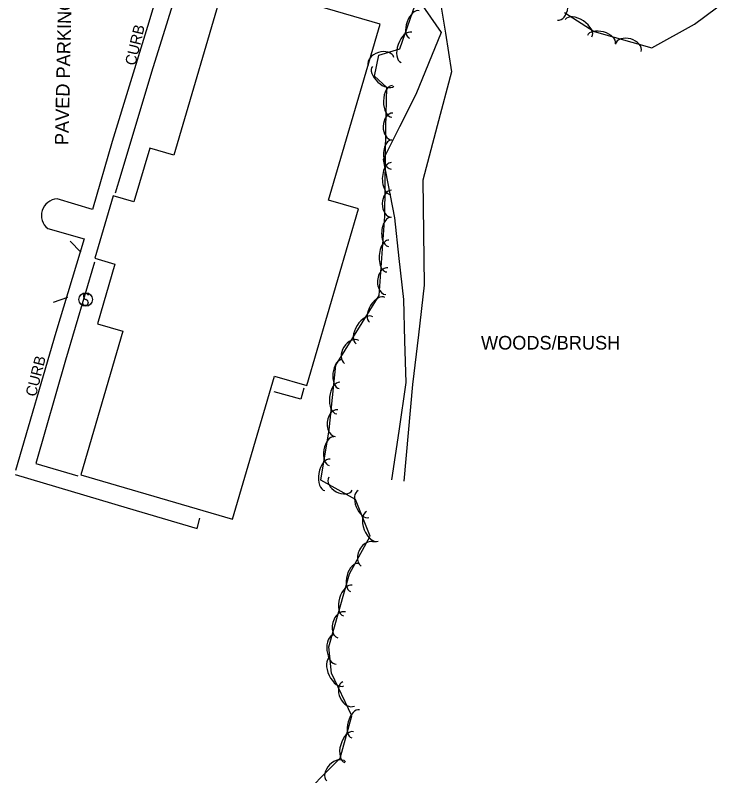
# Model space of a CAD drawing. Extents: x 978516 to 993312, y 1836504 to 1846212.
# Drawn here: x 992217.8 to 992474.8, y 1841361.8 to 1841641.6 of the extents above; entities that cross this region are included whole.
import ezdxf

# ---------------------------------------------------------------- set-up
doc = ezdxf.new("R2010")
doc.units = 0
for name, color, linetype in [('S_BUILDING', 7, 'Continuous'), ('S_CURB', 7, 'Continuous'), ('S_CURB_ANNOT', 7, 'Continuous'), ('S_PARKING', 7, 'Continuous'), ('S_PARKING_ANNOT', 7, 'Continuous'), ('S_SIDEWALK', 7, 'Continuous'), ('S_SIGN', 7, 'Continuous'), ('S_STREAM', 7, 'Continuous'), ('S_SURVEY_TEXT_ANNOT', 7, 'Continuous'), ('S_TREE', 7, 'Continuous')]:
    doc.layers.add(name, color=color, linetype=linetype)

msp = doc.modelspace()

# ---------------------------------------------------------------- linework, layer by layer
at = {"layer": 'S_BUILDING'}
msp.add_lwpolyline([(992295.19, 1841654.97), (992276.18, 1841590.11), (992267.27, 1841592.72), (992261.46, 1841572.9), (992253.87, 1841575.13), (992247.14, 1841552.19), (992254.47, 1841550.04), (992248.03, 1841528.07), (992257.43, 1841525.31), (992241.95, 1841472.52), (992297.77, 1841456.16), (992313.22, 1841508.85), (992325.09, 1841505.36), (992344.14, 1841570.36), (992333.06, 1841573.6), (992352.02, 1841638.31)], close=True, dxfattribs=at)
at = {"layer": 'S_CURB'}
for points in [[(992241.88, 1841554.44), (992237.97, 1841558.52)], [(992237.02, 1841537.8), (992231.7, 1841535.93)]]:
    msp.add_lwpolyline(points, dxfattribs=at)
at = {"layer": 'S_PARKING'}
for points in [[(992270.48, 1841694.38), (992281.96, 1841688.92), (992266.45, 1841637.41), (992253.5, 1841595.19), (992246.2, 1841570.07), (992233.19, 1841574.04)], [(992229.76, 1841563.11), (992243.1, 1841559.35), (992232.7, 1841524.85), (992217.88, 1841474.07)]]:
    msp.add_lwpolyline(points, dxfattribs=at)
msp.add_arc((992233.56, 1841567.92), 6.13, 93.4496, 231.6929, dxfattribs=at)
at = {"layer": 'S_SIDEWALK'}
for points in [[(992293.67, 1841654.91), (992279.9, 1841659.34), (992267.99, 1841620.64), (992256.59, 1841582.96), (992254.57, 1841576.2)], [(992246.96, 1841550.71), (992236.26, 1841514.68), (992225.32, 1841476.7), (992240.8, 1841472.12)], [(992323.95, 1841504.39), (992322.9, 1841500.34), (992313.05, 1841503)], [(992217.78, 1841472.61), (992258.99, 1841460.33), (992284.76, 1841452.72), (992285.74, 1841456.52)]]:
    msp.add_lwpolyline(points, dxfattribs=at)
at = {"layer": 'S_SIGN'}
msp.add_circle((992243.74, 1841537), 2.49, dxfattribs=at)
for centre, radius, start, end in [((992244.42, 1841538.33), 1.5, 167.1196, 241.9813), ((992243.81, 1841538.27), 0.95, 16.5258, 156.8957), ((992243.32, 1841535.66), 1.4, 358.6529, 73.7063), ((992243.58, 1841536.18), 1.28, 204.641, 335.359)]:
    msp.add_arc(centre, radius, start, end, dxfattribs=at)
at = {"layer": 'S_STREAM'}
for points in [[(992273.14, 1841723.34), (992280.91, 1841712.24), (992288.68, 1841701.14), (992309.73, 1841693.54), (992330.78, 1841685.93), (992345.76, 1841670.53), (992360.73, 1841655.13), (992374.51, 1841635.23), (992365.25, 1841612.49), (992359.21, 1841600.53), (992353.16, 1841588.56), (992357.3, 1841567.09), (992359, 1841552.08), (992360.7, 1841537.06), (992361.09, 1841521.8), (992361.48, 1841506.53), (992358.89, 1841488.58), (992356.29, 1841470.64)], [(992279.15, 1841723.05), (992299.02, 1841709.9), (992318.88, 1841696.74), (992330.75, 1841691.7), (992342.62, 1841686.67), (992351.74, 1841675.4), (992360.86, 1841664.14), (992373.77, 1841649.17), (992376.07, 1841634.98), (992378.37, 1841620.8), (992373.1, 1841600.86), (992367.83, 1841580.91), (992368.06, 1841561.59), (992368.3, 1841542.27), (992366.17, 1841524), (992364.03, 1841505.73), (992362.41, 1841487.93), (992360.79, 1841470.12)]]:
    msp.add_lwpolyline(points, dxfattribs=at)
at = {"layer": 'S_TREE'}
for points in [[(992419.97, 1841642.67), (992430.8, 1841635.64), (992452.11, 1841629.61), (992467.8, 1841638.34), (992487.8, 1841653.27)], [(992321.01, 1841351.83), (992337.31, 1841368.24), (992341.68, 1841383.78), (992334.14, 1841399.51), (992333.13, 1841409.25), (992340.82, 1841436.04), (992348.37, 1841449.95), (992342.99, 1841463.46), (992330.26, 1841470.56), (992333.35, 1841489.07), (992335.77, 1841512.81), (992351.75, 1841538.43), (992353.82, 1841567.69), (992354.2, 1841600.32), (992354.52, 1841615), (992350.03, 1841619.14), (992351.57, 1841626.88), (992359.3, 1841629.27), (992365, 1841645.4)]]:
    msp.add_lwpolyline(points, dxfattribs=at)
for centre, major_axis, ratio, start_param, end_param in [((992417.8, 1841644.69), (0.52, 4.93), 0.684432, 3.141593, 6.283185), ((992364.69, 1841638.16), (-1.78, -5.04), 0.540007, 3.141593, 6.283185), ((992425.09, 1841636.83), (-4.92, 3.2), 0.547716, 3.141593, 6.283185), ((992361.73, 1841629.8), (-1.96, -5.53), 0.549376, 3.141593, 6.283185), ((992433.53, 1841632.67), (-5.14, 1.46), 0.53871, 3.141593, 6.283185), ((992443.37, 1841629.62), (-4.77, 1.35), 0.682789, 3.141593, 6.283185), ((992352.41, 1841624.65), (-4.73, -1.46), 0.685052, 3.141593, 6.283185), ((992353.15, 1841619.16), (3.93, -3.63), 0.540555, 3.141593, 6.283185), ((992356.53, 1841609.92), (-0.13, -5.87), 0.549416, 3.141593, 6.283185), ((992356.58, 1841600.65), (-0.11, -4.95), 0.684484, 3.141593, 6.283185), ((992356.2, 1841590.38), (-0.06, -5.35), 0.540051, 3.141549, 6.283142), ((992356.1, 1841581.51), (-0.07, -5.87), 0.54942, 3.141548, 6.283141), ((992356.25, 1841572.25), (-0.06, -4.96), 0.684489, 3.14152, 6.283112), ((992355.53, 1841561.84), (-0.38, -5.33), 0.540044, 3.141343, 6.282936), ((992354.91, 1841552.99), (-0.41, -5.85), 0.549413, 3.141335, 6.282928), ((992354.51, 1841543.74), (-0.35, -4.94), 0.68448, 3.141171, 6.282764), ((992351, 1841533.23), (-2.83, -4.54), 0.540095, 3.141165, 6.282757), ((992346.31, 1841525.7), (-3.1, -4.98), 0.549465, 3.141151, 6.282743), ((992341.63, 1841517.71), (-2.62, -4.21), 0.684545, 3.14087, 6.282462), ((992337.57, 1841509.57), (-0.55, -5.31), 0.540437, 3.143089, 6.284681), ((992336.67, 1841500.76), (-0.6, -5.83), 0.549813, 3.143137, 6.284729), ((992335.99, 1841491.53), (-0.51, -4.93), 0.684978, 3.144121, 6.285714), ((992334.19, 1841481.23), (-0.88, -5.27), 0.540012, 3.141593, 6.283185), ((992332.73, 1841472.48), (-0.97, -5.79), 0.549381, 3.141593, 6.283185), ((992337.49, 1841469.26), (4.33, -2.41), 0.685263, 3.141593, 6.283185), ((992345.95, 1841461.76), (1.98, -4.97), 0.54026, 3.141593, 6.283185), ((992349.23, 1841453.52), (2.17, -5.45), 0.549632, 3.141593, 6.283185), ((992347.48, 1841443.31), (-2.36, -4.36), 0.684496, 3.141069, 6.282662), ((992342.66, 1841434.75), (-1.48, -5.13), 0.540559, 3.143354, 6.284946), ((992340.21, 1841426.24), (-1.62, -5.63), 0.549937, 3.143411, 6.285003), ((992337.91, 1841417.28), (-1.38, -4.76), 0.685131, 3.14457, 6.286163), ((992335.37, 1841408.21), (0.55, -5.32), 0.540098, 3.141593, 6.283185), ((992336.2, 1841400.12), (2.54, -5.29), 0.54968, 3.141593, 6.283185), ((992340.44, 1841391.88), (2.14, -4.47), 0.684812, 3.141593, 6.283185), ((992343.05, 1841380.84), (-1.44, -5.15), 0.540296, 3.140316, 6.281908), ((992340.65, 1841372.31), (-1.58, -5.65), 0.54967, 3.140275, 6.281867), ((992335.88, 1841363.42), (-3.49, -3.5), 0.685459, 3.144412, 6.286004)]:
    msp.add_ellipse(centre, major_axis=major_axis, ratio=ratio, start_param=start_param, end_param=end_param, dxfattribs=at)

# ---------------------------------------------------------------- texts
at = {"layer": 'S_CURB_ANNOT'}
for rotation, p in [(76.6855, (992262.01, 1841622.86)), (75.866, (992225.39, 1841501.02))]:
    msp.add_text('CURB', height=4, rotation=rotation, dxfattribs=at).set_placement(p)
at = {"layer": 'S_PARKING_ANNOT'}
msp.add_text('PAVED PARKING', height=5.0005, rotation=88.7241, dxfattribs=at).set_placement((992237.35, 1841593.76))
at = {"layer": 'S_SURVEY_TEXT_ANNOT'}
msp.add_text('WOODS/BRUSH', height=5, dxfattribs=at).set_placement((992389.17, 1841518.61))

doc.saveas('drawing.dxf')
